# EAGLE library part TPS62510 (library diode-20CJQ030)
Ti's TPS62510 1.5-A, LOW VI HIGH EFFICIENCY STEP-DOWN CONVERTER Description: The TPS62510 family are high-efficiency step-down converters targeted for operation from a 1.8-V to 3.8-V input voltage rail, ideally suited for 2-cell Alkaline or NiMHd applications. The TPS62510 is also ideal as a point-of-load regulator running from a fixed 3.3-V, 2.5-V or 1.8-V input voltage rail. The converter operates in fixed frequency PWM mode switching at 1.5 MHz with the MODE pin high. Pulling the MODE pin low enables the high efficiency mode. In high efficiency mode, the device operates with a 1.5 MHz fixed frequency PWM at nominal load current, and automatically enters the Power Save Mode at light load currents. For maximum system reliability, the converter features Output Voltage Tracking using the OVT pin to allow sequencing, and to allow for the output voltage to track an external voltage applied to this pin. Features: 1.8-V to 3.8-V Input Voltage Range Up to 96% High Efficiency Synchronous Step-Down Converter 1.5-MHz Fixed Frequency PWM Operation 1% Output Voltage Accuracy in Fixed Frequency PWM Mode Power Save Mode Operation for High Efficiency Over the Entire Load Current Range 22-mA Quiescent Current Fixed and Adjustable Output Voltage Output Voltage Tracking (OVT) for Reliable Sequencing Available in a 10-Pin QFN (3 x 3 mm) Package Applications: Portable Devices (Mobile Phone, PDA) 2-Cell NiMHd/Alkaline Applications Hard Disc Drives Point-Of-Load Regulation Notebook Computers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
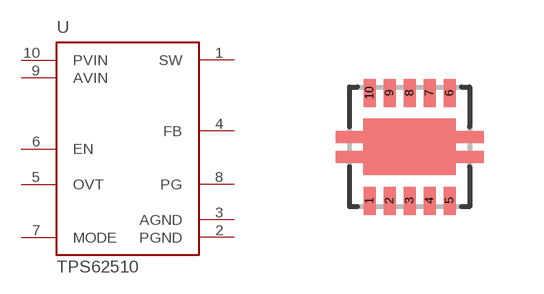
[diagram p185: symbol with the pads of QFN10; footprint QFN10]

Designator prefix U

## TPS62510DRC  [QFN10]
1  SW
2  PGND  pwr
3  AGND  pwr
4  FB
5  OVT  pwr
6  EN  in
7  MODE  in
8  PG
9  AVIN  pwr
10  PVIN  pwr

## Footprint QFN10 (pad centres in mm)
QFN10 for Ti's TPS6204x
smd 0.3 x 0.7: 1 -1,-1.35; 2 -0.5,-1.35; 3 0,-1.35; 4 0.5,-1.35; 5 1,-1.35; 6 1,1.35; 7 0.5,1.35; 8 0,1.35; 9 -0.5,1.35; 10 -1,1.35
